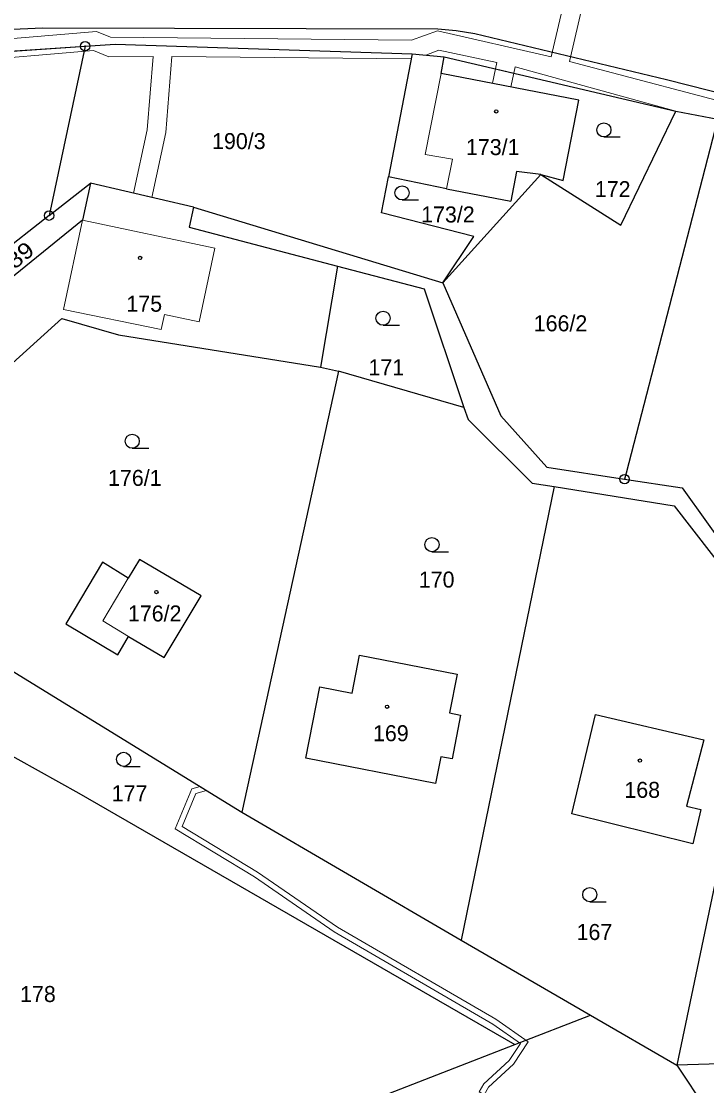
# Model space of a CAD drawing. Extents: x -727701 to -724405, y -960481 to -957284.
# Drawn here: x -726703 to -726630.1, y -958207.9 to -958094.8 of the extents above; entities that cross this region are included whole.
import ezdxf
from ezdxf.enums import TextEntityAlignment as Align

# ---------------------------------------------------------------- set-up
doc = ezdxf.new("R2010")
doc.units = 0
doc.header["$LTSCALE"] = 0.68
for name, color, linetype, lineweight in [('1', 7, 'Continuous', 25), ('13', 7, 'Continuous', 13), ('3', 7, 'Continuous', 25), ('4', 7, 'Continuous', 13), ('5', 7, 'Continuous', 25), ('8', 7, 'Continuous', 25)]:
    doc.layers.add(name, color=color, linetype=linetype, lineweight=lineweight)
doc.layers.add('2', color=7, linetype='Continuous')

msp = doc.modelspace()

# ---------------------------------------------------------------- linework, layer by layer
at = {"layer": '1'}
for p, q in [((-726707.69, -958095.76), (-726700.68, -958095.47)), ((-726700.68, -958095.47), (-726658.72, -958095.58)), ((-726658.72, -958095.58), (-726656.77, -958095.74)), ((-726656.77, -958095.74), (-726654.79, -958096.07)), ((-726654.79, -958096.07), (-726634.4, -958100.95)), ((-726710.03, -958098.34), (-726696.2, -958097.41)), ((-726696.2, -958097.41), (-726700.03, -958115.42)), ((-726696.2, -958097.41), (-726693, -958097.2)), ((-726693, -958097.2), (-726661.42, -958098.23)), ((-726661.42, -958098.23), (-726663.95, -958111.28)), ((-726661.42, -958098.23), (-726658.02, -958098.53)), ((-726658.36, -958100.3), (-726658.02, -958098.53)), ((-726658.02, -958098.53), (-726633.4, -958104.3)), ((-726643.73, -958103.13), (-726658.36, -958100.3)), ((-726634.4, -958100.95), (-726566.79, -958118.23)), ((-726645.39, -958111.69), (-726643.73, -958103.13)), ((-726639.25, -958116.45), (-726633.4, -958104.3)), ((-726633.4, -958104.3), (-726628.95, -958105.15)), ((-726628.97, -958105.23), (-726638.69, -958142.79)), ((-726664.7, -958115.11), (-726663.95, -958111.28)), ((-726657.78, -958112.56), (-726663.95, -958111.28)), ((-726658.18, -958122.56), (-726647.75, -958111.05)), ((-726650.33, -958110.72), (-726650.95, -958113.89)), ((-726647.75, -958111.05), (-726650.33, -958110.72)), ((-726647.75, -958111.05), (-726639.25, -958116.45)), ((-726647.75, -958111.05), (-726645.39, -958111.69)), ((-726700.03, -958115.42), (-726695.64, -958111.98)), ((-726695.64, -958111.98), (-726696.47, -958115.89)), ((-726684.69, -958114.51), (-726695.64, -958111.98)), ((-726657.78, -958112.56), (-726650.95, -958113.89)), ((-726684.69, -958114.51), (-726685.15, -958116.66)), ((-726700.03, -958115.42), (-726709.09, -958122.51)), ((-726696.47, -958115.89), (-726706, -958123.6)), ((-726654.9, -958117.65), (-726664.7, -958115.11)), ((-726685.15, -958116.66), (-726669.36, -958120.79)), ((-726669.36, -958120.79), (-726671.18, -958131.52)), ((-726669.36, -958120.79), (-726660.17, -958123.19)), ((-726658.18, -958122.56), (-726652, -958136.7)), ((-726660.17, -958123.19), (-726655.95, -958135.8)), ((-726705.06, -958132.13), (-726698.69, -958126.37)), ((-726671.18, -958131.52), (-726669.26, -958131.94)), ((-726669.26, -958131.94), (-726679.54, -958178.82)), ((-726655.95, -958135.8), (-726669.26, -958131.94)), ((-726655.95, -958135.8), (-726655.5, -958137.1)), ((-726655.5, -958137.1), (-726648.7, -958143.84)), ((-726652, -958136.7), (-726647.12, -958142.17)), ((-726647.12, -958142.17), (-726638.86, -958143.42)), ((-726638.69, -958142.79), (-726638.86, -958143.42)), ((-726646.33, -958144.22), (-726656.23, -958192.42)), ((-726648.7, -958143.84), (-726646.33, -958144.22)), ((-726646.33, -958144.22), (-726633.59, -958146.25)), ((-726638.86, -958143.42), (-726632.73, -958144.34)), ((-726632.73, -958144.34), (-726626.43, -958153.22)), ((-726633.59, -958146.25), (-726625.75, -958156.4)), ((-726690.43, -958151.96), (-726691.61, -958153.94)), ((-726683.87, -958155.84), (-726690.43, -958151.96)), ((-726694.35, -958152.24), (-726698.25, -958158.81)), ((-726691.61, -958153.94), (-726694.35, -958152.24)), ((-726687.78, -958162.39), (-726683.87, -958155.84)), ((-726623.26, -958157.59), (-726633.29, -958205.71)), ((-726698.25, -958158.81), (-726692.73, -958162.11)), ((-726692.73, -958162.11), (-726691.58, -958160.14)), ((-726691.58, -958160.14), (-726687.78, -958162.39)), ((-726707.63, -958161.54), (-726679.54, -958178.82)), ((-726667.83, -958166.16), (-726667.04, -958162.13)), ((-726667.04, -958162.13), (-726656.66, -958164.17)), ((-726656.66, -958164.17), (-726657.47, -958168.28)), ((-726672.74, -958173.07), (-726671.25, -958165.49)), ((-726671.25, -958165.49), (-726667.83, -958166.16)), ((-726657.47, -958168.28), (-726656.29, -958168.51)), ((-726656.29, -958168.51), (-726657.2, -958173.17)), ((-726644.48, -958178.99), (-726641.96, -958168.45)), ((-726641.96, -958168.45), (-726630.43, -958171.15)), ((-726710.12, -958169.45), (-726696.88, -958176.81)), ((-726630.43, -958171.15), (-726632.28, -958178.2)), ((-726658.94, -958175.78), (-726672.74, -958173.07)), ((-726658.38, -958172.94), (-726658.94, -958175.78)), ((-726657.2, -958173.17), (-726658.38, -958172.94)), ((-726696.88, -958176.81), (-726650.53, -958203.52)), ((-726632.28, -958178.2), (-726630.74, -958178.56)), ((-726679.54, -958178.82), (-726656.23, -958192.42)), ((-726631.59, -958182.18), (-726644.48, -958178.99)), ((-726630.74, -958178.56), (-726631.59, -958182.18)), ((-726656.23, -958192.42), (-726642.47, -958200.39)), ((-726650.53, -958203.52), (-726642.47, -958200.39)), ((-726642.47, -958200.39), (-726633.29, -958205.71)), ((-726698.6, -958222.18), (-726650.53, -958203.52)), ((-726594.48, -958204.65), (-726633.29, -958205.71)), ((-726633.29, -958205.71), (-726622.75, -958221.7))]:
    msp.add_line(p, q, dxfattribs=at)
for points in [[(-726684.69, -958114.51), (-726658.18, -958122.56), (-726654.9, -958117.65)], [(-726698.69, -958126.37), (-726692.64, -958128.1), (-726671.18, -958131.52)]]:
    msp.add_lwpolyline(points, dxfattribs=at)
at = {"layer": '13'}
for points in [[(-726604.4, -958109.65), (-726644.73, -958099.04), (-726642.31, -958088.63), (-726644.3, -958088.37), (-726646.67, -958098.54), (-726658.74, -958095.77), (-726661.5, -958096.77), (-726693.5, -958096.46), (-726694.99, -958095.83), (-726709.76, -958097.1), (-726711.37, -958097.43), (-726710.03, -958098.34), (-726693, -958097.2), (-726661.42, -958098.23), (-726660, -958098.35), (-726658.6, -958097.84), (-726652.45, -958099.16), (-726652.59, -958099.8), (-726650.64, -958100.26), (-726650.5, -958099.62), (-726633.4, -958104.3), (-726628.95, -958105.15)], [(-726709.48, -958099.08), (-726695.31, -958097.86), (-726693.68, -958098.55), (-726688.98, -958098.52), (-726689.6, -958106.31), (-726691.06, -958113.04), (-726689.11, -958113.49), (-726687.62, -958106.6), (-726686.98, -958098.52), (-726661.53, -958098.77), (-726661.42, -958098.23), (-726693, -958097.2), (-726710.03, -958098.34)]]:
    msp.add_lwpolyline(points, dxfattribs=at)
for points in [[(-726652.59, -958099.8), (-726652.91, -958101.35), (-726650.95, -958101.73), (-726650.64, -958100.26)], [(-726683.98, -958176.09), (-726684.86, -958176.33), (-726686.62, -958180.59), (-726678.19, -958185.71), (-726669.71, -958191.56), (-726652.85, -958201.35), (-726649.93, -958203.4), (-726651.14, -958205.22), (-726653.81, -958207.69), (-726654.31, -958208.57), (-726653.79, -958208.86), (-726653.33, -958208.07), (-726650.68, -958205.62), (-726649.1, -958203.24), (-726652.53, -958200.84), (-726669.38, -958191.05), (-726677.87, -958185.21), (-726685.87, -958180.34), (-726684.42, -958176.83), (-726683.29, -958176.52)]]:
    msp.add_lwpolyline(points, close=True, dxfattribs=at)
at = {"layer": '3'}
for p, q in [((-726641.063, -958107.06), (-726639.313, -958107.06)), ((-726662.513, -958113.75), (-726660.763, -958113.75)), ((-726664.533, -958127.07), (-726662.783, -958127.07)), ((-726691.193, -958140.15), (-726689.443, -958140.15)), ((-726659.333, -958151.14), (-726657.583, -958151.14)), ((-726692.103, -958173.96), (-726690.353, -958173.96)), ((-726642.563, -958188.34), (-726640.813, -958188.34))]:
    msp.add_line(p, q, dxfattribs=at)
for centre in [(-726641.0629, -958106.3098), (-726662.5129, -958112.9998), (-726664.5329, -958126.3198), (-726691.1929, -958139.3998), (-726659.3329, -958150.3898), (-726692.1029, -958173.2098), (-726642.5629, -958187.5898)]:
    msp.add_circle(centre, 0.75, dxfattribs=at)
at = {"layer": '4'}
for p, q in [((-726660.04, -958108.93), (-726658.36, -958100.3)), ((-726657.16, -958109.4), (-726660.04, -958108.93)), ((-726657.78, -958112.56), (-726657.16, -958109.4)), ((-726698.49, -958125.4), (-726696.47, -958115.89)), ((-726696.47, -958115.89), (-726682.4, -958118.88)), ((-726682.4, -958118.88), (-726684.06, -958126.72)), ((-726698.49, -958125.4), (-726688.1, -958127.51)), ((-726687.76, -958125.93), (-726688.1, -958127.51)), ((-726684.06, -958126.72), (-726687.76, -958125.93)), ((-726691.61, -958153.94), (-726694.33, -958158.5)), ((-726694.33, -958158.5), (-726691.58, -958160.14))]:
    msp.add_line(p, q, dxfattribs=at)
at = {"layer": '5'}
for centre in [(-726652.5068, -958104.3492), (-726690.3568, -958119.9192), (-726688.6268, -958155.4292), (-726664.0968, -958167.6192), (-726637.2368, -958173.3492)]:
    msp.add_circle(centre, 0.175, dxfattribs=at)
at = {"layer": '8'}
for centre, radius in [((-726696.2, -958097.4099), 0.5), ((-726696.2, -958097.4099), 0.0303), ((-726700.03, -958115.4199), 0.5), ((-726700.03, -958115.4199), 0.0303), ((-726638.86, -958143.4199), 0.5), ((-726638.86, -958143.4199), 0.0303)]:
    msp.add_circle(centre, radius, dxfattribs=at)

# ---------------------------------------------------------------- texts
at = {"layer": '2'}
for s, p in [('190/3', (-726679.86, -958108.345)), ('166/2', (-726645.67, -958127.715))]:
    msp.add_text(s, height=1.7, dxfattribs=at).set_placement(p, align=Align.CENTER)
for s, p in [('173/1', (-726655.72, -958108.985)), ('172', (-726642.02, -958113.455)), ('173/2', (-726660.48, -958116.145)), ('175', (-726691.81, -958125.635)), ('171', (-726666.08, -958132.395)), ('176/1', (-726693.76, -958144.145)), ('170', (-726660.73, -958154.955)), ('176/2', (-726691.65, -958158.555)), ('169', (-726665.6, -958171.285)), ('177', (-726693.37, -958177.665)), ('168', (-726638.88, -958177.305)), ('167', (-726643.96, -958192.415)), ('178', (-726703.11, -958199.005))]:
    msp.add_text(s, height=1.7, dxfattribs=at).set_placement(p)
at = {"layer": '2', "width": 1.15}
msp.add_text('189', height=1.7, rotation=39, dxfattribs=at).set_placement((-726704.832, -958122.11))

doc.saveas('drawing.dxf')
